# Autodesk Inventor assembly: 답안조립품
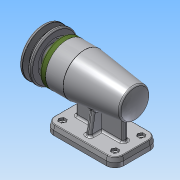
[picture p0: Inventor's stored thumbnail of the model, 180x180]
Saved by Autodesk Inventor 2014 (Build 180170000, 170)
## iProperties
Created: 2017-01
Part Number: 답안조립품
Document SubType Name: Assembly
Designer: 702
Author: 702
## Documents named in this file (12)
- C:\Users\702\Desktop\470107V1012\답안조립품.iam
- C:\Users\702\Desktop\470107V1012\본체.ipt
- C:\Users\702\Desktop\470107V1012\커버.ipt
- C:\Users\702\Desktop\470107V1012\오일 실.ipt
- C:\Users\702\Desktop\470107V1012\베어링 6004.ipt
- C:\Users\702\Desktop\470107V1012\축.ipt
- C:\Users\702\Desktop\470107V1012\어댑터슬리브.ipt
- C:\Users\702\Desktop\470107V1012\볼트 M4 x 12.ipt
- C:\Users\702\Desktop\470107V1012\베어링 51202.ipt
- C:\Users\702\Desktop\470107V1012\V벨트풀리.ipt
- C:\Users\702\Desktop\470107V1012\키 5 x 5 x 16.ipt
- C:\Users\702\Desktop\470107V1012\멈춤나사 M3x8.ipt
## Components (6 placed, 2 different names)
1. ISO 4762 M4 x 12:1
2. V벨트풀리:1 — 각도:1
3. ISO 4762 M4 x 12:2
4. ISO 4762 M4 x 12:3
5. ISO 4762 M4 x 12:4
6. ISO 4762 M4 x 12:5
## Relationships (1: Angle 1)
- 각도:1 [Angle]: V벨트풀리:1
